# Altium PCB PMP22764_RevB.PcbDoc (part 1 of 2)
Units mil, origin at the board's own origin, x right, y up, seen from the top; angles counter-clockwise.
Board outline 2750 x 1770 mil, 4 copper layers (Top Layer, Signal Layer 1, Signal Layer 2, Bottom Layer), stack 61.2 mil thick; 76 components, 35 nets, 197 pads, 92 vias.
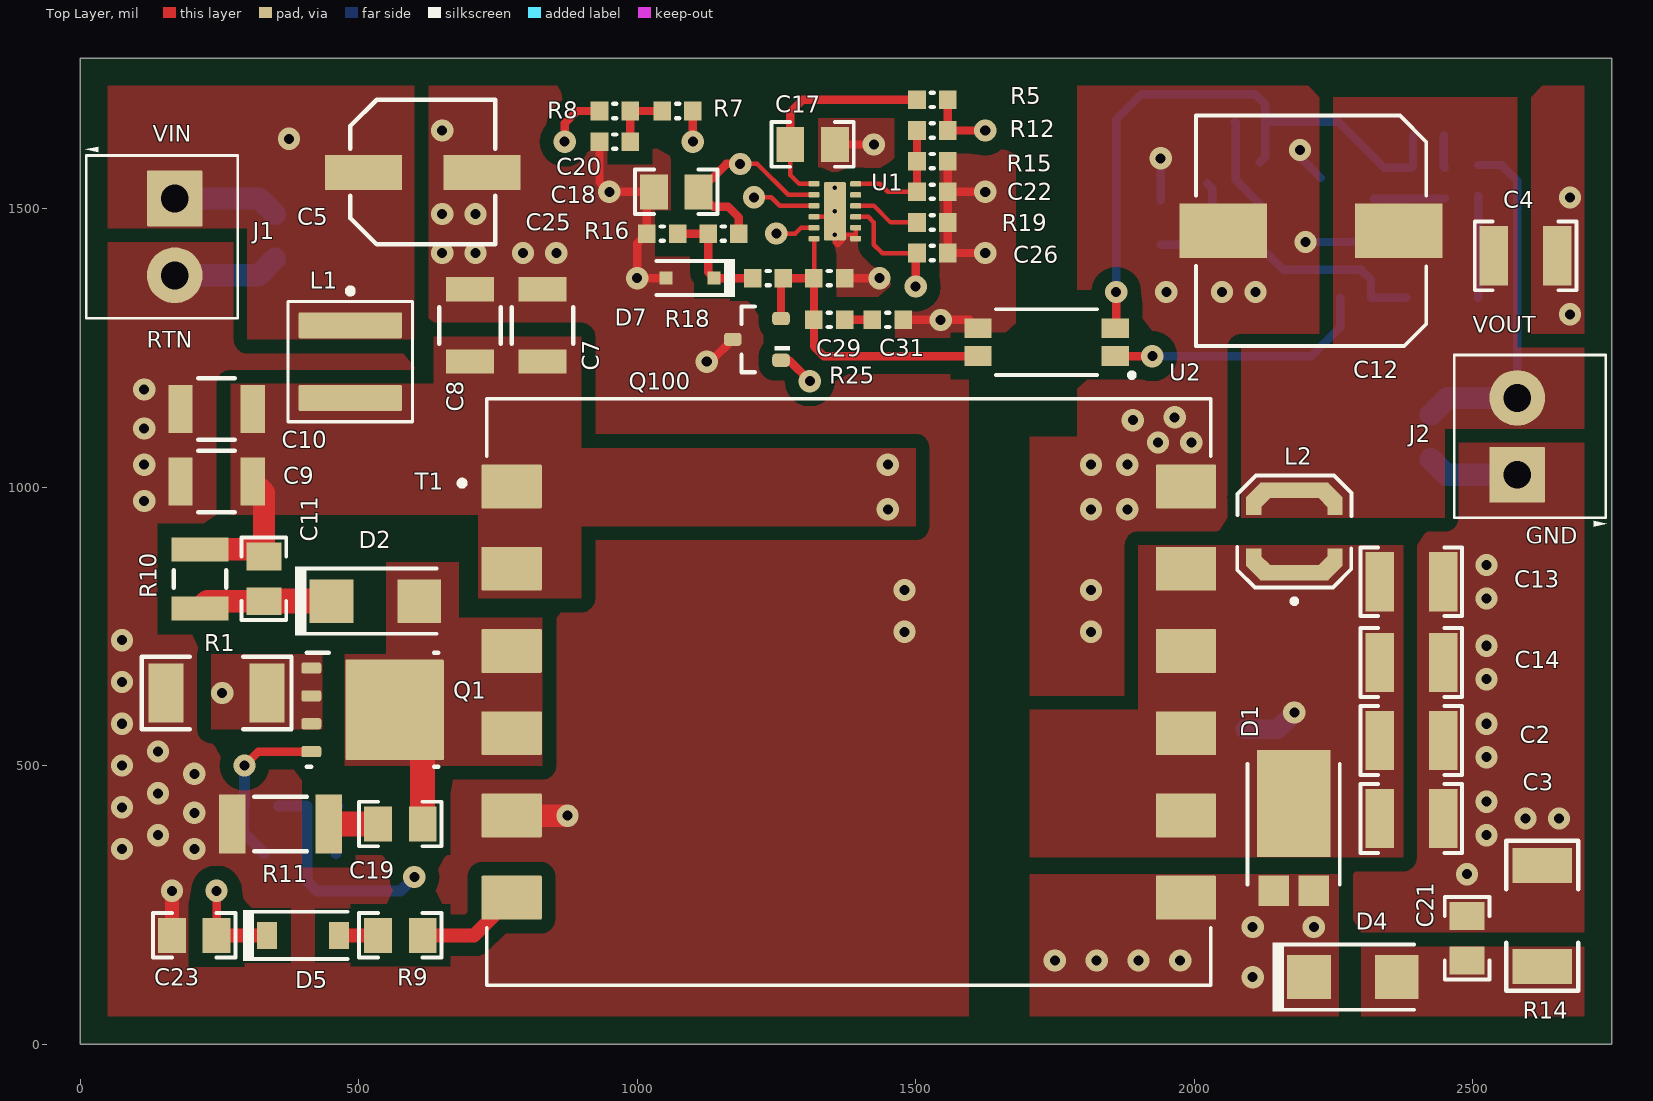
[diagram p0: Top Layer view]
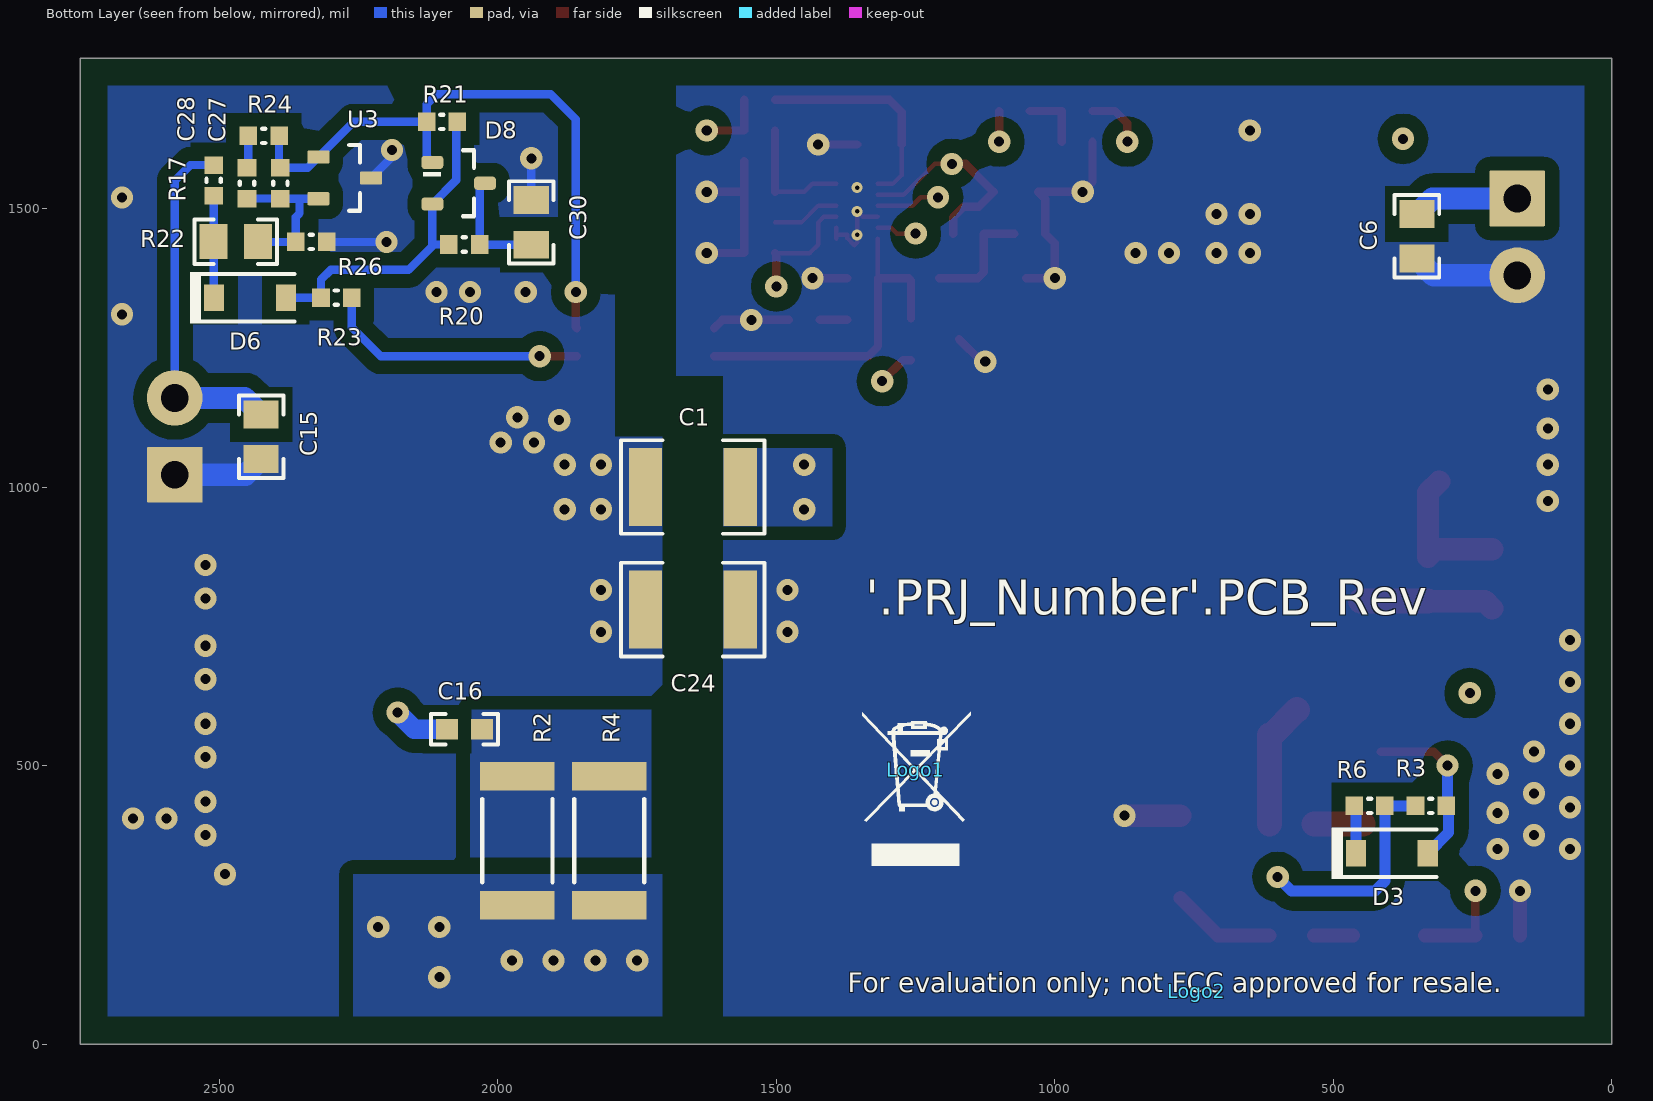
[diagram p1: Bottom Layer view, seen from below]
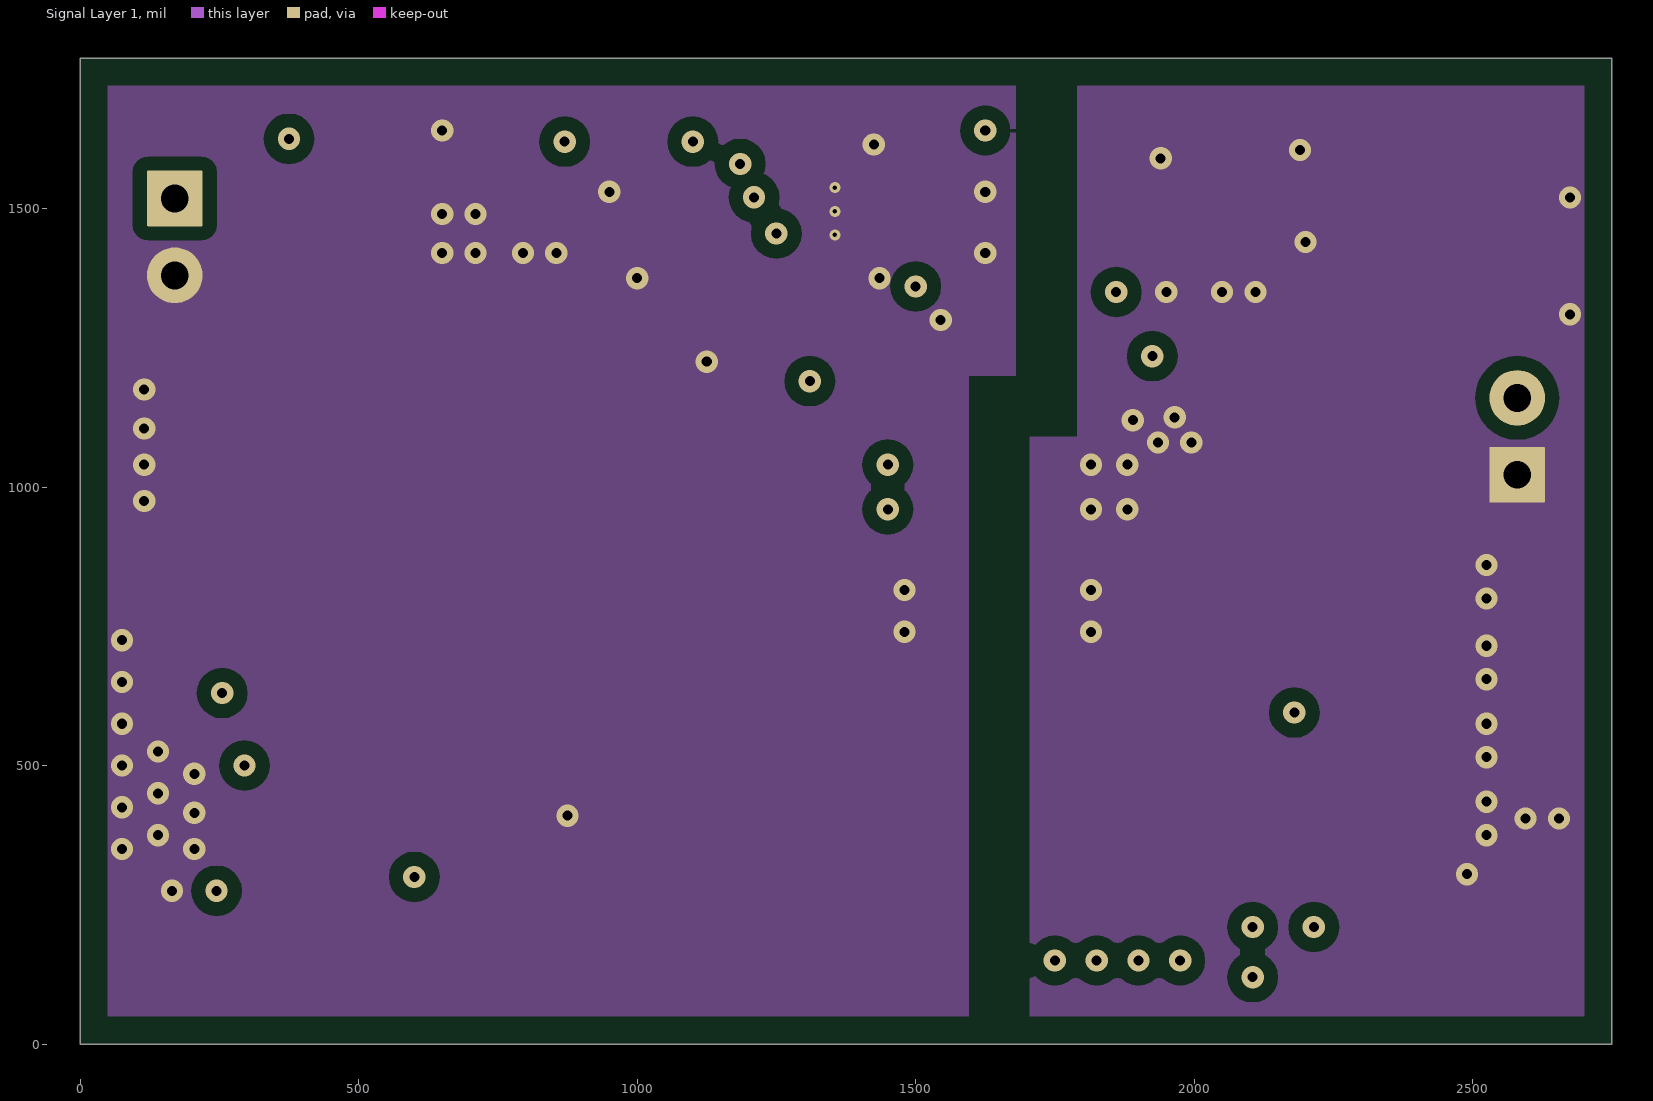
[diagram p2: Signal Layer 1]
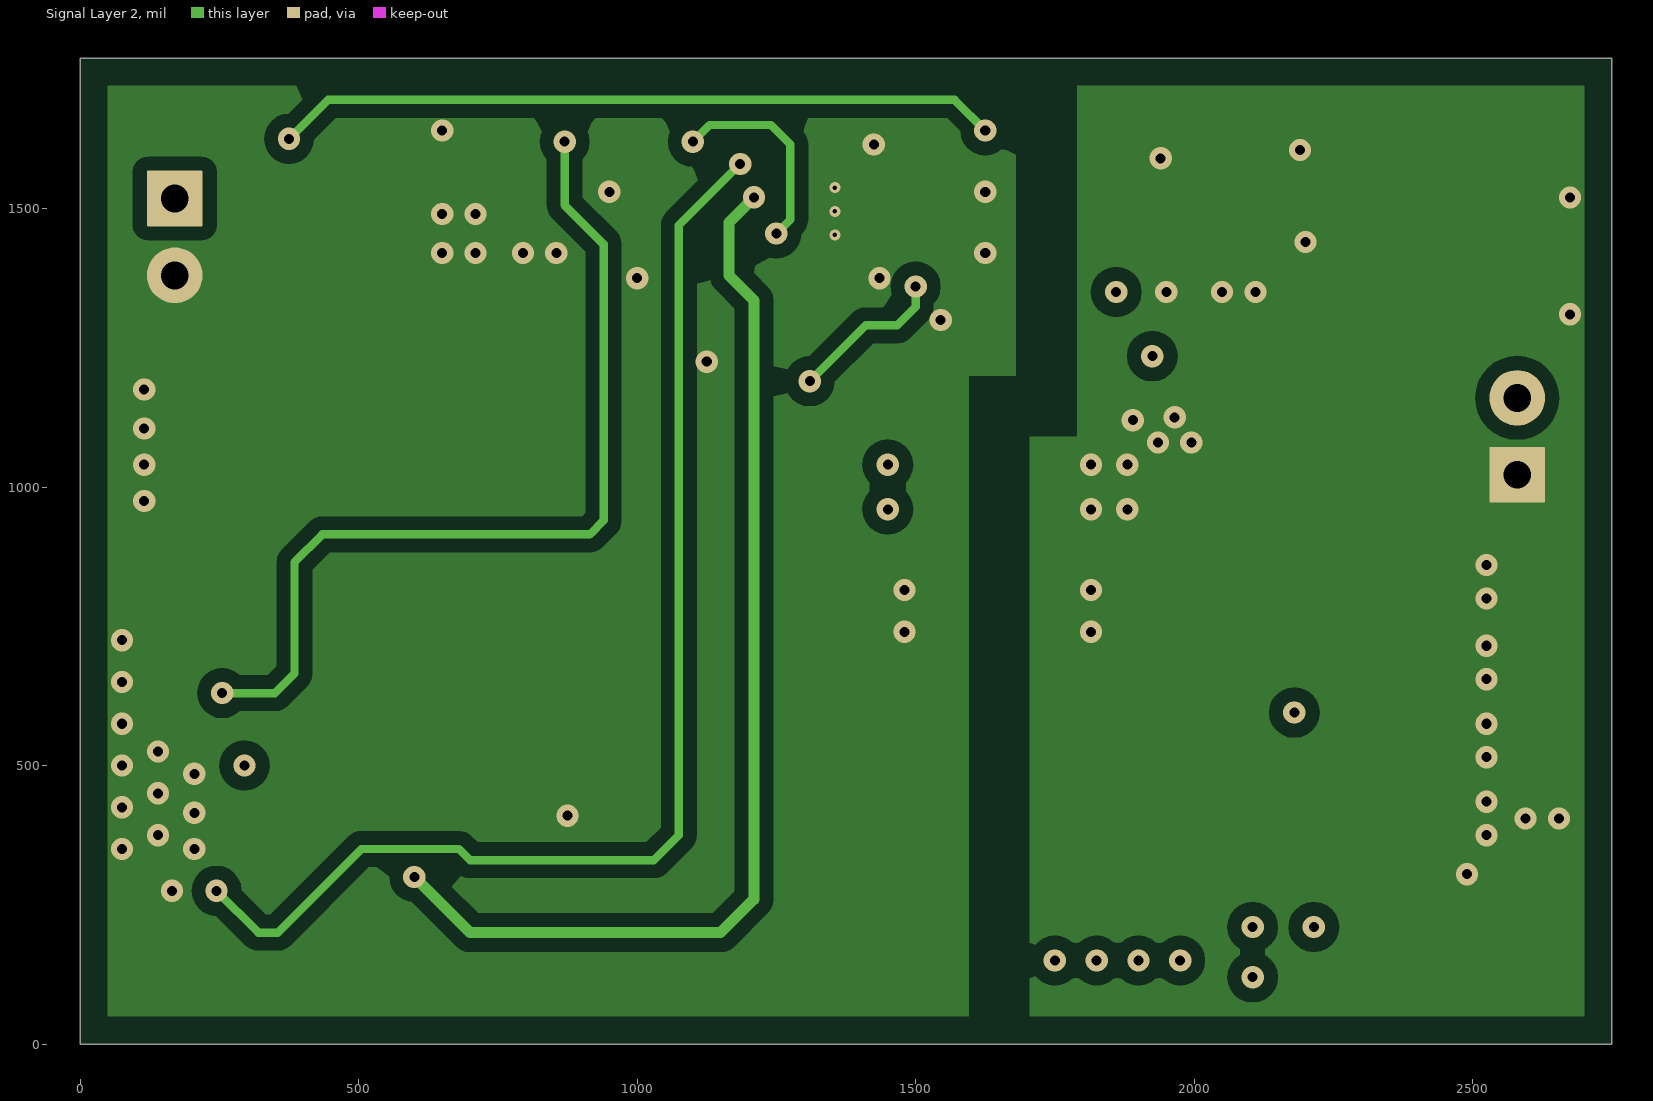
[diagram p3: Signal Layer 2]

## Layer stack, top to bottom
Top Solder: solder mask 0.4, Solder Resist, Dk 3.5
Top Layer: signal copper 2.8
Dielectric1: core 15, FR-4, Dk 4.8
Signal Layer 1: signal copper 2.8
Dielectric 2: prepreg 20, Dk 4.2
Signal Layer 2: signal copper 2.8
Dielectric 3: core 15, FR-4, Dk 4.2
Bottom Layer: signal copper 2.8
Bottom Solder: solder mask 0.4, Solder Resist, Dk 3.5

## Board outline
0,0 2750,0 2750,1770 0,1770

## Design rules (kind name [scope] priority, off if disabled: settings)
AcuteAngle [All] p1: minimum=4.50000000000000E+0001 checktracksonly=FALSE
AssemblyTestPointUsage [All] p1: valid=2
BoardOutlineClearance BoardOutlineClearance_MountingHoles [OnCopper and InComponentClass('Mounting Holes')] p1: gap=39.37 ignorepadtopadclearanceinfootprint=FALSE
BoardOutlineClearance BoardOutlineClearance_Poly [OnCopper and IsPoly] p2: gap=25 ignorepadtopadclearanceinfootprint=FALSE
BoardOutlineClearance [OnCopper and Not InComponentClass('Logo') and not InComponentClass('FiducialMark') and not InRegion(1000,500,4000,800) and not InPoly] p3: gap=50 ignorepadtopadclearanceinfootprint=FALSE
Clearance Clearance_Keepouts [((IsTrack Or IsArc) And Not InPoly) And IsFree and IsKeepOut vs ((IsTrack Or IsArc) And Not InPoly) And IsFree and IsKeepOut] p1: gap=0 ignorepadtopadclearanceinfootprint=FALSE
Clearance Clearance_Poly [InPolygon] p2: gap=25 ignorepadtopadclearanceinfootprint=TRUE
Clearance Clearance_FiducialMark [IsKeepOut and InComponentClass('FiducialMark') vs IsPad and InComponentClass('FiducialMark')] p3: gap=0 ignorepadtopadclearanceinfootprint=FALSE
Clearance [All] p4: gap=7.87 ignorepadtopadclearanceinfootprint=TRUE
ComponentClearance ComponentClearance_MountingHoles_FiducialMarks [InComponentClass('Mounting Holes') vs InComponentClass('FiducialMark')] p1: gap=50 collisioncheckmode=3 verticalgap=10 showdistances=FALSE
ComponentClearance ComponentClearance_Shunt [InComponentClass('Header') vs InComponentClass('Shunt')] p2: gap=0 collisioncheckmode=3 verticalgap=0 showdistances=FALSE
ComponentClearance ComponentClearance_Logo [InComponentClass('Logo')] p3: gap=50 collisioncheckmode=3 verticalgap=10 showdistances=FALSE
ComponentClearance ComponentClearance_ScrewToNut [(HasFootprint('NY PMS 440 0025 PH')) vs (HasFootprint('Keystone_1902C'))] p4: gap=5 collisioncheckmode=3 verticalgap=10 showdistances=FALSE
ComponentClearance ComponentClearance_MountingHoles [InComponentClass('Mounting Holes')] p5: gap=250 collisioncheckmode=3 verticalgap=100000 showdistances=FALSE
ComponentClearance ComponentClearance_SmallPassives [HasFootprint('0201*') or HasFootprint('0402*') or HasFootprint('0508') or HasFootprint('0603*') or HasFootprint('0612') or HasFootprint('0805*') or HasFootprint('0815*') or HasFootprint('0830*') or HasFootprint('1206*') or HasFootprint('1210*') or HasFootprint('1808*') or HasFootprint('1812*') or HasFootprint('1825*') or HasFootprint('2010*') or HasFootprint('2220*') or HasFootprint('2225*') or HasFootprint('2512*') or HasFootprint('2728*') or HasFootprint('3518*') vs HasFootprint('0201*') or HasFootprint('0402*') or HasFootprint('0508') or HasFootprint('0603*') or HasFootprint('0612') or HasFootprint('0805*') or HasFootprint('0815*') or HasFootprint('0830*') or HasFootprint('1206*') or HasFootprint('1210*') or HasFootprint('1808*') or HasFootprint('1812*') or HasFootprint('1825*') or HasFootprint('2010*') or HasFootprint('2220*') or HasFootprint('2225*') or HasFootprint('2512*') or HasFootprint('2728*') or HasFootprint('3518*')] p6: gap=14.96 collisioncheckmode=3 verticalgap=10 showdistances=FALSE
ComponentClearance ComponentClearance_THtoSMT [IsThruComponent vs IsSMTComponent] p7: gap=40 collisioncheckmode=3 verticalgap=30 showdistances=FALSE
ComponentClearance ComponentClearance_THtoTH [IsThruComponent vs IsThruComponent] p8: gap=30 collisioncheckmode=3 verticalgap=30 showdistances=FALSE
ComponentClearance [All] p9: gap=30 collisioncheckmode=3 verticalgap=10 showdistances=FALSE
DiffPairsRouting [All] p1: maxlimit=100 minlimit=10 mostfreqgap=10 toplayer_minwidth=15 toplayer_maxwidth=15 toplayer_prefwidth=15 midlayer1_minwidth=15 midlayer1_maxwidth=15 midlayer1_prefwidth=15 midlayer2_minwidth=15 midlayer2_maxwidth=15 midlayer2_prefwidth=15 bottomlayer_minwidth=15 bottomlayer_maxwidth=15 bottomlayer_prefwidth=15 maxuncoupledlength=1000
FabricationTestPointUsage TestPointUsage [All] p1: valid=2 allowmultiple=FALSE
FabricationTestpoint Testpoint [All] p1: side=3 testpointundercomponent=TRUE minsize=40 maxsize=100 preferedsize=60 minholesize=0 maxholesize=40 preferedholesize=32 testpointgrid=1 allowsidetop=TRUE allowsidebottom=TRUE usegrid=TRUE gridtolerance=0.01
FanoutControl Fanout_LCC [IsLCC] p1: bgadir=Out bgaviamode=Centered fanoutstyle=Auto fanoutdirection=Alternating viagrid=1 // Fanout_LCC (Default Rule)
FanoutControl Fanout_BGA [IsBGA] p2: bgadir=Out bgaviamode=Centered fanoutstyle=Auto fanoutdirection=Alternating viagrid=1 // Fanout_BGA (Default Rule)
FanoutControl Fanout_Default [All] p4: bgadir=Out bgaviamode=Centered fanoutstyle=Auto fanoutdirection=Alternating viagrid=1 // Fanout_Default (Default Rule)
FanoutControl Fanout_Small [(CompPinCount < 5)] p5: bgadir=Out bgaviamode=Centered fanoutstyle=Auto fanoutdirection=OutThenIn viagrid=1 // Fanout_Small (Default Rule)
HoleSize [All] p1: absolutevalues=TRUE maxlimit=251 minlimit=7.87 maxpercent=80.000 minpercent=20.000
MinimumAnnularRing MinimumAnnularRing_ThermalPadVias [IsVia and InAnyComponent] p1: minimumring=5.91
MinimumAnnularRing [All] p2: minimumring=7.87
MinimumSolderMaskSliver MinimumSolderMaskSliver_Logo [InComponentClass('Logo') vs InComponentClass('Logo')] p1: minsoldermaskwidth=0.7
MinimumSolderMaskSliver [All] p2: minsoldermaskwidth=3.94
PlaneConnect [All] p1: planeconnectstyle=Relief reliefexpansion=10 reliefentries=4 reliefconductorwidth=10 reliefairgap=10
PolygonConnect [All] p1: connectstyle=Direct reliefconductorwidth=10 reliefentries=4 polygonreliefangle="90 Angle" airgapwidth=10
RoutingVias ThermalPadVias [IsVia and InAnyComponent] p1: holewidth=7.87 width=19.68 viastyle="Through Hole" minholewidth=7.87 minwidth=19.68 maxholewidth=12.99 maxwidth=23.62
RoutingVias [All] p2: holewidth=18 width=40 viastyle="Through Hole" minholewidth=7.87 minwidth=26 maxholewidth=40 maxwidth=65
SilkToBoardRegionClearance [Not ((IsComment or IsDesignator) And (Hide <> 'False')) and not InRegion(1000,500,4000,800)] p1:
SilkToSilkClearance SilkToSilkClearance_Pb-FreeLogo [(HasFootprint('Pb-Free_Overlay_Medium') OR HasFootprint('Pb-Free_Overlay_Small')) vs (HasFootprint('Pb-Free_Overlay_Medium') OR HasFootprint('Pb-Free_Overlay_Small'))] p1: silktosilkclearance=0
SilkToSilkClearance [All] p2: silktosilkclearance=3.94
SilkToSolderMaskClearance SilkToComponentPadClearance [(IsPad or IsFill or IsRegion) and InAnycomponent] p1: minsilkscreentomaskgap=5 clearancetoexposedcopper=TRUE
SilkToSolderMaskClearance "Silk to Solder Mask Opening" [All] p2: minsilkscreentomaskgap=3.94 clearancetoexposedcopper=FALSE
SolderMaskExpansion [All] p1: expansion=1.97
UnRoutedNet [All] p1: checkbadconnections=TRUE
Width [All] p1: maxlimit=100 minlimit=6 preferedwidth=10 checkconnectedcopper=TRUE
14 further rules are at their usual default settings.

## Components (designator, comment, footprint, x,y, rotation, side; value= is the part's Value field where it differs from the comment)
C1 "Capacitor" 1812_HV 1650,1000 r180 bottom value=2200pF
C2 "Capacitor" 1210_270 2390,545 r180 top value=2.2uF
C3 "Capacitor" 1210_270 2390,405 r180 top value=2.2uF
C4 "Capacitor" 1210_270 2595,1415 r180 top value=2.2uF
C5 "EEHZC1V470P" SM_RADIAL_6.3AMM 615,1565 r0 top value=47uF
C6 "UMK212B7224KG-T" 0805_HV 350,1450 r270 bottom value=0.22uF
C7 "UMK325AB7106KM-T" 1210_280 830,1290 r90 top value=10uF
C8 "UMK325AB7106KM-T" 1210_280 700,1290 r90 top value=10uF
C9 "UMK325AB7106KM-T" 1210_280 245,1010 r180 top value=10uF
C10 "UMK325AB7106KM-T" 1210_280 245,1140 r180 top value=10uF
C11 "UMK212B7224KG-T" 0805_HV 330,835 r270 top value=0.22uF
C12 "EEHZC1J560P" SM_RADIAL_10BMM 2210,1460 r180 top value=56uF
C13 "Capacitor" 1210_270 2390,830 r0 top value=2.2uF
C14 "Capacitor" 1210_270 2390,685 r0 top value=2.2uF
C15 "Capacitor" 0805_HV 2425,1090 r90 bottom value=0.1uF
C16 "C1608C0G2E221J080AA" 0603 2060,565 r180 bottom value=220pF
C17 "UMK212B7224KG-T" 0805_HV 1315,1615 r180 top value=0.22uF
C18 "TMK212B7105KG-T" 0805_HV 1070,1530 r180 top value=1uF
C19 "Capacitor" 0805_HV 575,395 r180 top value=100pF
C20 "885012206081" 0603L 960,1620 r0 top value=470pF
C21 "QMK212B7103KG-T" 0805_HV 2490,190 r90 top value=0.01uF
C22 "GRM1885C1H470JA01D" 0603L 1530,1530 r180 top value=47pF
C23 "TMK212B7105KG-T" 0805_HV 205,195 r0 top value=1uF
C24 "Capacitor" 1812_HV 1650,780 r180 bottom value=2200pF
C25 "885012206071" 0603L 1045,1455 r180 top value=0.1uF
C26 "C1608X7R1E224K080AC" 0603L 1530,1420 r0 top value=0.22uF
C27 "C0603C220J5GACTU" 0603L 2390.39,1545.46 r90 bottom value=22pF
C28 "GRM188R71E473KA01D" 0603L 2450.39,1545.46 r90 bottom value=0.047uF
C29 "885012206083" 0603L 1345,1375 r180 top value=1000pF
C30 "TMK212B7105KG-T" 0805_HV 1940,1475 r270 bottom value=1uF
C31 "885012206071" 0603L 1450,1300 r0 top value=0.1uF
D1 "PDU620-13" POWERDI5 2178.78,353.39 r90 top value=200V
D2 "ES2DA-13-F" SMA 530,795 r0 top value=200V
D3 "MMSD4148T1G" SOD-123 395,342.5 r180 bottom value=100V
D4 "ES2DA-13-F" SMA 2285,120 r0 top value=200V
D5 "MMSD4148T1G" SOD-123 400,195 r0 top value=100V
D6 "MMSZ5259B-7-F" SOD-123 2445,1340 r180 bottom value=39V
D7 "MMSZ5231BS-7-F" SOD-323 1095,1375 r180 top value=5.1V
D8 "BAT54S-7-F" SOT-23 2070.39,1545.46 r180 bottom value=30V
J1 "ED555/2DS" TERM_BLK_ED555-2DS 170,1518 r270 top
J2 "Receptacle_2x1" TERM_BLK_ED555-2DS 2580,1022 r90 top
L1 "XEL5050-332MEB" FP-XEL5050-332MEB_SMT_IND_5MM48_5MM28-MFG 485,1225 r270 top value=3.3uH
L2 "LPS4012-331MLB" LPS4012 2180,920 r90 top value=330nH
Logo1 "WEEE logo" WEEE_Minimum 1250,492.22 r180 bottom
Logo2 "FCC disclaimer" FCC_disclaimer 745,95 r180 bottom
Q1 "CSD19531Q5A" DQJ0008A 525.04,600 r0 top value=100V
Q100 "FMMT718TA" SOT-23L 1215,1265 r180 top value="20 V"
R1 "RC1210JR-0710KL" 1210L 215,835 r270 top value=10k
R2 "CRCW251268R0JNEG" 2512 1965,365 r90 bottom value=68
R3 "CRCW060320R0JNEA" 0603L 325,427.5 r180 bottom value=20
R4 "CRCW251268R0JNEG" 2512 1800,365 r90 bottom value=68
R5 "Resistor" 0603L 1530,1695 r0 top value=0
R6 "Resistor" 0603L 435,427.5 r0 bottom value=0
R7 "Resistor" 0603L 1072.56,1675 r180 top value=0
R8 "CRCW0603301RFKEA" 0603L 960,1675 r180 top value=301
R9 "CRCW080510R0JNEA" 0805_HV 575,195 r180 top value=10
R10 "PMR50HZPFU10L0" 2010 245,630 r0 top value=0.01
R11 "Resistor" 2010L 360,395 r0 top value=75
R12 "CRCW0603324KFKEA" 0603L 1530,1640 r180 top value=324k
R14 "CRCW201039K0JNEF" 2010 2625,230 r90 top value=39k
R15 "CRCW060329K4FKEA" 0603L 1530,1585 r0 top value=29.4k
R16 "CRCW06031K00FKEA" 0603L 1155,1455 r0 top value=1.00k
R17 "Resistor" 0603L 2510.39,1550.46 r270 bottom value=0
R18 "CRCW06032K49FKEA" 0603L 1235,1375 r0 top value=2.49k
R19 "CRCW060386K6FKEA" 0603L 1530,1475 r0 top value=86.6k
R20 "CRCW060310K0FKEA" 0603L 2060.39,1435.46 r180 bottom value=10.0k
R21 "CRCW060310K0FKEA" 0603L 2100.39,1655.46 r0 bottom value=10.0k
R22 "CRCW080549K9FKEA" 0805_HV 2470.39,1440.46 r180 bottom value=49.9k
R23 "CRCW06032K49FKEA" 0603L 2290,1340 r180 bottom value=2.49k
R24 "CRCW060340K2FKEA" 0603L 2420.39,1630.46 r0 bottom value=40.2k
R25 "CRCW06031K00FKEA" 0603L 1345,1300 r180 top value=1.00k
R26 "CRCW06032K32FKEA" 0603L 2335,1440 r180 bottom value=2.32k
T1 "ZB1368-AL" FP-ZB1368-AL_PTH_XFRMR_33MM02_26MM75-MFG 1380,631.85 r0 top
U1 "LM51551DSSR" DSS0012B 1355,1495 r0 top
U2 "VOS617A-7X001T" SSOP-4_VISHAY 1735,1260 r180 top
U3 "TL431LIAIDBZR" DBZ0003A_N 2275,1555 r180 bottom

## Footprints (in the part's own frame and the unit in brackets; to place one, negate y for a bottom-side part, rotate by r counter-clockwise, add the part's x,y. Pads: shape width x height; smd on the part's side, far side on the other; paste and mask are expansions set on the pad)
0603 [mm] "0603 from SM-752 data"
  rect 1x0.95 smd: 1(-0.8,0) 2(0.8,0)
  silkscreen extent -1.52,-0.69 1.52,0.69, body extent -0.87,-0.47 0.87,0.47, height 1
0603L [mm] "0603 from SM-752 data"
  rect 0.8x0.85 smd: 1(-0.7,0) 2(0.7,0)
  silkscreen extent -0.07,-0.33 0.07,0.33, body extent -0.87,-0.47 0.87,0.47, height 1
0805_HV [mil] "0805 with 30mil clearance between pads"
  rect 50x63 smd: 1(-40,0) 2(40,0)
  silkscreen extent -74,-40 74,40, body extent -43,-29 43,29, height 57
1210_270 [mm] "1210"
  rect 1.3x2.7 smd: 1(-1.45,0) 2(1.45,0)
  silkscreen extent -2.32,-1.57 2.32,1.57, body extent -1.7,-1.35 1.7,1.35, height 2.7
1210_280 [mm] "SMD, 2-Leads, Body 3.6x2.8mm, Height 2.8mm"
  rect 1.1x2.2 smd: 1(-1.65,0) 2(1.65,0)
  silkscreen extent -0.84,-1.4 0.84,1.4, body extent -1.8,-1.4 1.8,1.4, height 2.8
1210L [mm] "1210 from SM-752 data"
  rect 1.1x2.6 smd: 1(-1.35,0) 2(1.35,0)
  silkscreen extent -0.4,-1.2 0.4,1.2, body extent -1.7,-1.35 1.7,1.35, height 1.35
1812_HV [mil] "PRG recommended land pattern"
  rect 60x140 smd: 1(-85,0) 2(85,0)
  silkscreen extent -129,-84 129,84, body extent -94,-67 94,67, height 53
2010 [mm] "Chip Capacitor, Body 5.08x2.54mm, IPC Medium Density"
  rect 1.6x2.7 smd: 1(-2.3,0) 2(2.3,0)
  silkscreen extent -3.42,-1.65 3.42,1.65, body extent -2.73,-1.45 2.73,1.45, height 1.66
2010L [mm]
  rect 1.2x2.7 smd: 1(-2.2,0) 2(2.2,0)
  silkscreen extent -1.2,-1.25 1.2,1.25, body extent -2.73,-1.45 2.73,1.45, height 1.66
2512 [mm] "Chip Resistor, Body 6.3x3.2mm, IPC Medium Density"
  rect 1.3x3.4 smd: 1(-2.95,0) 2(2.95,0)
  silkscreen extent -1.9,-1.6 1.9,1.6, body extent -3.22,-1.67 3.22,1.67, height 0.71
DBZ0003A_N [mm] "SOT23, 3-Leads, Body 2.9x1.3mm, Pitch 0.95mm, Lead Span 2.4mm, IPC Medium Density"
  rrect17% 1x0.6 smd: 1(-1.2,0.95) 2(-1.2,-0.95) 3(1.2,0)
  silkscreen extent 0.2,-1.5 0.7,1.5, body extent -1.26,-1.46 1.26,1.46, height 0.98
DQJ0008A [mm] "SMD, 8-Leads, Body 5.75x4.9mm"
  rrect39% 0.91x0.51 smd paste-0.05 mask-0.05: 1(-2.795,1.905) 2(-2.795,0.635) 3(-2.795,-0.635) 4(-2.795,-1.905) 5(2.795,-1.905) 6(2.795,-0.635) 7(2.795,0.635) 8(2.795,1.905)
  rrect8% 1.58x1.25 on Top Paste: 9(-0.38,-1.45) 9(-0.38,0) 9(-0.38,1.45) 9(1.4,-1.45) 9(1.4,0) 9(1.4,1.45)
  rrect3% 3.48x4.47 on Top Solder: 9(0.55,0)
  rrect2% 4.49x4.57 smd paste-2.5 mask-2.5: 9(1.005,0)
  silkscreen extent -3,-2.6 3,2.6, body extent -3.13,-2.45 3.13,2.45, height 1.15
DSS0012B [mm] "WSON-10"
  rrect40% 0.5x0.25 smd: 1(-0.95,1.25) 2(-0.95,0.75) 3(-0.95,0.25) 4(-0.95,-0.25) 5(-0.95,-0.75) 6(-0.95,-1.25) 7(0.95,-1.25) 8(0.95,-0.75) 9(0.95,-0.25) 10(0.95,0.25) 11(0.95,0.75) 12(0.95,1.25)
  rrect11% 1x2.65 smd paste-0.5: 13(0,0)
  body extent -1,-1.5 1,1.5, height 0.81
FCC_disclaimer [mil]
FP-XEL5050-332MEB_SMT_IND_5MM48_5MM28-MFG [mm]
  rrect8% 1.18x4.7 smd paste+0 mask+0: 1(-1.655,0) 2(1.655,0)
  silkscreen extent -3.35,-2.84 2.74,2.84, body extent -2.84,-2.94 2.84,2.94, height 0.25
FP-ZB1368-AL_PTH_XFRMR_33MM02_26MM75-MFG [mm]
  rrect5% 2.75x2 smd paste+0 mask+0: 1(-15.375,9.375) 2(-15.375,5.625) 3(-15.375,1.875) 4(-15.375,-1.875) 5(-15.375,-5.625) 6(-15.375,-9.375) 7(15.375,-9.375) 8(15.375,-5.625) 9(15.375,-1.875) 10(15.375,1.875) 11(15.375,5.625) 12(15.375,9.375)
  silkscreen extent -17.76,-13.37 16.51,13.37, body extent -16.85,-13.47 16.85,13.47, height 0.25
LPS4012 [mm] "Coilcraft recommended land pattern.  Document 433-2, rev 10/20/08"
  rect 0.7x3.124 smd: 1(-1.881,0) 2(1.881,0)
  rect 0.902x0.801 smd rot 45: 1(-1.592,1.605) 2(1.592,-1.605)
  rect 0.902x0.801 smd rot 135: 1(-1.592,-1.605) 2(1.592,1.605)
  rect 0.812x0.7 smd: 1(-1.168,1.85) 1(-1.168,-1.85) 2(1.168,1.85) 2(1.168,-1.85)
  silkscreen extent -3.26,-2.6 2.55,2.6, body extent -2.05,-2.05 2.05,2.05, height 1.22
POWERDI5 [mm] "Diodes Inc recommended land pattern, ap02001.pdf rev 60"
  rect 1.4x1.39 smd: 1(-1.991,0.92) 2(-1.991,-0.92)
  rect 4.86x3.36 smd: 3(1.991,0)
  silkscreen extent -1.7,-2.1 3.8,2.1, body extent -2.27,-2.03 4.33,2.03, height 1.17
SM_RADIAL_6.3AMM [mm] "Nichicon 6.3x5.8"
  rect 3.5x1.6 smd: 1(-2.7,0) 2(2.7,0)
  silkscreen extent -3.3,-3.29 3.3,3.31, body extent -3.5,-3.3 3.5,3.3, height 6.11
SM_RADIAL_10BMM [mm] "Nichicon 10x10"
  rect 4x2.5 smd: 1(-4,0) 2(4,0)
  silkscreen extent -5.25,-5.25 5.25,5.25, body extent -5.25,-5.25 5.25,5.25, height 10.5
SMA [mm] "Molded Diode, 2-Leads, Body 4.3x2.6mm, IPC Medium Density, based on OnSemi component dimensions and land pattern"
  rect 2x2 smd: 1(-2,0) 2(2,0)
  silkscreen extent -3.66,-1.57 2.79,1.57, body extent -2.6,-1.3 2.6,1.3, height 2.42
SOD-123 [mm] "On Semi recommended land pattern"
  rect 0.915x1.22 smd: 1(-1.637,0) 2(1.637,0)
  silkscreen extent -2.74,-1.17 2.03,1.17, body extent -1.93,-0.9 1.93,0.9, height 1.35
SOD-323 [mm] "NXP recommended land pattern"
  rect 0.6x0.6 smd paste-0.05: 1(-1.1,0) 2(1.1,0)
  silkscreen extent -2.06,-0.86 1.53,0.86, body extent -1.3,-0.67 1.3,0.68, height 1.1
SOT-23 [mm] "SOT23, 3-Leads, Body 2.9x1.3mm, Pitch 0.95mm, Lead Span 2.5mm, IPC Medium Density"
  rrect50% 1x0.6 smd: 1(-1.2,0.95) 2(-1.2,-0.95) 3(1.2,0)
  silkscreen extent -1.63,-1.5 0.7,1.5, body extent -1.16,-1.45 1.21,1.45, height 1
SOT-23L [mm] "SOT23, 3-Leads, Body 2.9x1.3mm, Pitch 0.95mm, Lead Span 2.5mm, IPC High Density"
  rrect50% 0.8x0.6 smd: 1(-1.1,0.95) 2(-1.1,-0.95) 3(1.1,0)
  silkscreen extent -1.5,-1.5 0.7,1.5, body extent -1.16,-1.45 1.21,1.45, height 1
SSOP-4_VISHAY [mm] "Vishay Recommened"
  rect 1.25x0.9 smd: 1(-3.125,0.635) 2(-3.125,-0.635) 3(3.125,-0.635) 4(3.125,0.635)
  silkscreen extent -3.98,-1.5 2.3,1.59, body extent -3.5,-1.45 3.5,1.45, height 2.42
TERM_BLK_ED555-2DS [mil]
  rrect4% 100x100 hole 50: 1(0,0)
  round 100 hole 50: 2(138,0)
  silkscreen extent -93,-161 215,113, body extent -69,-150 207,106, height 323
WEEE_Minimum [mil] "WEEElie bin"
  silkscreen extent -95,-172 99,104

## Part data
C1 C24: library part CMP-0009358-2, "CAP, CERM, 2200 pF, 2000 V, +/- 10%, X7R, 1812", Cap_Case=1812, Manufacturer=TDK, PartNumber=C4532X7R3D222K130KA, Supplier Part Number 1=445-2389-1-ND, TempCo=X7R, Tolerance_%=10%, Value1=Unknown, Value2=2000V, ValueDisplayed=2200pF
C2 C3 C4 C13 C14: library part CMP-0009232-2, "CAP, CERM, 2.2 uF, 100 V, +/- 10%, X7R, 1210", Cap_Case=1210, Manufacturer=MuRata, PartNumber=GRM32ER72A225KA35L, Supplier Part Number 1=490-3385-1-ND, TempCo=X7R, Tolerance_%=10%, Value1="0.007 ohm", Value2=100V, ValueDisplayed=2.2uF
C5: library part CMP-0012607-3, "CAP, Polymer Hybrid, 47 uF, 35 V, +/- 20%, 60 ohm, 6.3x5.8 SMD", Manufacturer=Panasonic, Supplier Part Number 1=P15473CT-ND, Tolerance_%=20%, Value1="60 ohm", Value2=35V, ValueDisplayed=47uF
C6 C11 C17: library part CMP-0008422-2, "CAP, CERM, 0.22 uF, 50 V, +/- 10%, X7R, 0805", Cap_Case=0805, Manufacturer="Taiyo Yuden", Supplier Part Number 1=587-1287-1-ND, TempCo=X7R, Tolerance_%=10%, Value1=Unknown, Value2=50V, ValueDisplayed=0.22uF
C7 C8 C9 C10: library part CMP-0009259-2, "CAP, CERM, 10 uF, 50 V, +/- 10%, X7R, 1210", Cap_Case=1210, Manufacturer="Taiyo Yuden", Supplier Part Number 1=587-3167-1-ND, TempCo=X7R, Tolerance_%=10%, Value1=Unknown, Value2=50V, ValueDisplayed=10uF
C12: library part CMP-0012603-3, "CAP, Polymer Hybrid, 56 uF, 63 V, +/- 20%, 30 ohm, 10x10 SMD", Manufacturer=Panasonic, Supplier Part Number 1=P15469CT-ND, Tolerance_%=20%, Value1="30 ohm", Value2=63V, ValueDisplayed=56uF
C15: library part CMP-0007886-2, "CAP, CERM, 0.1 uF, 100 V, +/- 10%, X7R, 0805", Cap_Case=0805, Manufacturer=TDK, PartNumber=C2012X7R2A104K125AA, Supplier Part Number 1=445-1418-1-ND, TempCo=X7R, Tolerance_%=10%, Value1="0.020726 ohm", Value2=100V, ValueDisplayed=0.1uF
C16: library part CMP-0006996-4, "CAP, CERM, 220 pF, 250 V, +/- 5%, C0G/NP0, 0603", Cap_Case=0603, Manufacturer=TDK, Supplier Part Number 1=445-2316-1-ND, TempCo=C0G/NP0, Tolerance_%=5%, Value1=Unknown, Value2=250V, ValueDisplayed=220pF
C18 C23 C30: library part CMP-0008412-2, "CAP, CERM, 1 uF, 25 V, +/- 10%, X7R, 0805", Cap_Case=0805, Manufacturer="Taiyo Yuden", Supplier Part Number 1=587-1281-1-ND, TempCo=X7R, Tolerance_%=10%, Value1=Unknown, Value2=25V, ValueDisplayed=1uF
C19: library part CMP-0008236-2, "CAP, CERM, 100 pF, 250 V, +/- 5%, C0G/NP0, 0805", Cap_Case=0805, Manufacturer=MuRata, PartNumber=GRM21A5C2E101JW01D, Supplier Part Number 1=490-5542-1-ND, TempCo=C0G/NP0, Tolerance_%=5%, Value1=Unknown, Value2=250V, ValueDisplayed=100pF
C20: library part CMP-0006834-5, "CAP, CERM, 470 pF, 50 V, +/- 10%, X7R, 0603", Cap_Case=0603, Manufacturer="Wurth Elektronik", Supplier Part Number 1=710-885012206081, TempCo=X7R, Tolerance_%=10%, Value1=Unknown, Value2=50V, ValueDisplayed=470pF
C21: library part CMP-0008408-2, "CAP, CERM, 0.01 uF, 250 V, +/- 10%, X7R, 0805", Cap_Case=0805, Manufacturer="Taiyo Yuden", Supplier Part Number 1=587-1271-1-ND, TempCo=X7R, Tolerance_%=10%, Value1=Unknown, Value2=250V, ValueDisplayed=0.01uF
C22: library part CMP-0007220-4, "CAP, CERM, 47 pF, 50 V, +/- 5%, C0G/NP0, 0603", Cap_Case=0603, Manufacturer=MuRata, Supplier Part Number 1=490-1419-1-ND, TempCo=C0G/NP0, Tolerance_%=5%, Value1=Unknown, Value2=50V, ValueDisplayed=47pF
C25 C31: library part CMP-0006832-5, "CAP, CERM, 0.1 uF, 25 V, +/- 10%, X7R, 0603", Cap_Case=0603, Manufacturer="Wurth Elektronik", Supplier Part Number 1=710-885012206071, TempCo=X7R, Tolerance_%=10%, Value1=Unknown, Value2=25V, ValueDisplayed=0.1uF
C26: library part CMP-0007042-4, "CAP, CERM, 0.22 uF, 25 V, +/- 10%, X7R, 0603", Cap_Case=0603, Manufacturer=TDK, Supplier Part Number 1=445-5191-1-ND, TempCo=X7R, Tolerance_%=10%, Value1=Unknown, Value2=25V, ValueDisplayed=0.22uF
C27: library part CMP-0006892-4, "CAP, CERM, 22 pF, 50 V, +/- 5%, C0G/NP0, 0603", Cap_Case=0603, Manufacturer=Kemet, Supplier Part Number 1=399-1053-1-ND, TempCo=C0G/NP0, Tolerance_%=5%, Value1=Unknown, Value2=50V, ValueDisplayed=22pF
C28: library part CMP-0007423-4, "CAP, CERM, 0.047 uF, 25 V, +/- 10%, X7R, 0603", Cap_Case=0603, Manufacturer=MuRata, Supplier Part Number 1=490-1522-1-ND, TempCo=X7R, Tolerance_%=10%, Value1=Unknown, Value2=25V, ValueDisplayed=0.047uF
C29: library part CMP-0064933-4, "CAP, CERM, 1000 pF, 50 V,+/- 10%, X7R, 0603", Cap_Case=0603, Manufacturer="Wurth Elektronik", Supplier Part Number 1=732-8001-1-ND, TempCo=X7R, Tolerance_%=10%, Value1=Unknown, Value2=50V, ValueDisplayed=1000pF
D1: library part CMP-0077019-2, "Diode, Ultrafast, 200 V, 6 A, PowerDI5", Manufacturer="Diodes Inc.", Value1=6A, Value2=0.94V
D2 D4: library part CMP-0076892-2, "Diode, Superfast Rectifier, 200 V, 2 A, SMA", Manufacturer="Diodes Inc.", Value1=2A, Value2=0.92V
D3 D5: library part CMP-0029032-2, "Diode, Switching, 100 V, 0.2 A, SOD-123", Manufacturer="ON Semiconductor", Value1=0.2A, Value2=1V
D6: library part CMP-0005764-4, "Diode, Zener, 39 V, 500 mW, SOD-123", Manufacturer="Diodes Inc.", Power_W=500mW, Value1=0.5W
D7: library part CMP-0005854-3, "Diode, Zener, 5.1 V, 200 mW, SOD-323", Manufacturer="Diodes Inc.", Power_W=200mW, Value1=0.2W
D8: library part CMP-0028456-2, "Diode, Schottky, 30 V, 0.2 A, SOT-23", Manufacturer="Diodes Inc.", Value1=0.2A, Value2=0.65V
J1: library part CMP-0074913-1, "Terminal Block, 3.5mm Pitch, 2x1, TH", Color=Grey, Current_A=6A, Manufacturer="On-Shore Technology", Supplier Part Number 1=ED1514-ND, Voltage_V=150V
J2: library part CMP-0074913-1, "Terminal Block, 3.5mm Pitch, 2x1, TH", Color=Grey, Current_A=6A, Manufacturer="On-Shore Technology", PartNumber=ED555/2DS, Supplier Part Number 1=ED1514-ND, Voltage_V=150V
L1: library part CMP-0090124-1, "Shielded Power Inductor, 3.3uH, ±20%, 7.8A, 14.6mO max", Manufacturer=Coilcraft, Operating Temperature Range="to +165°C", Self Resonant Frequency=31MHz, Test Frequency=1MHz, Tolerance_%=20%
L2: library part CMP-0060464-1, "Inductor, Shielded Drum Core, Ferrite, 330 nH, 3 A, 0.03 ohm, SMD", Manufacturer=Coilcraft, Value1="0.03 ohm", Value2=3A, ValueDisplayed=330nH
Logo1: library part CMP-0074769-1
Logo2: library part CMP-0074847-1, "FCC_disclaimer"
Q1: library part CMP-0000956-2, "MOSFET, N-CH, 100 V, 16 A, DQJ0008A (VSONP-8)", Alternate Manufacturer=None, Manufacturer="Texas Instruments", Supplier Part Number 1=CSD19531Q5A-ND, Value2="36 nC"
Q100: library part CMP-0000330-2, "Transistor, PNP, 20 V, 1.5 A, SOT-23", Manufacturer="Diodes Inc.", Supplier Part Number 1=FMMT718CT-ND, Value1="1.5 A", Value2=6
R1: library part CMP-0083442-1, "RES, 10 k, 5%, 0.5 W, 1210", Manufacturer=Yageo, Power_W=500mW, TempCo="100 ppm/C", Tolerance_%=5%, Value2=0.5W, Value_Code=10k0, ValueDisplayed=10k
R2 R4: library part CMP-0015995-3, "RES, 68, 5%, 1 W, AEC-Q200 Grade 0, 2512", Manufacturer=Vishay-Dale, Power_W=1W, Supplier Part Number 1=541-68XCT-ND, TempCo="200 ppm/C", Tolerance_%=5%, Value_Code=68R0, ValueDisplayed=68
R3: library part CMP-0025754-4, "RES, 20, 5%, 0.1 W, AEC-Q200 Grade 0, 0603", Manufacturer=Vishay-Dale, Power_W=100mW, Supplier Part Number 1=541-20GCT-ND, TempCo="200 ppm/C", Tolerance_%=5%, Value2=0.1W, Value_Code=20R0, ValueDisplayed=20
R5 R6 R7 R17: library part CMP-0025697-4, "RES, 0, 5%, 0.1 W, AEC-Q200 Grade 0, 0603", Manufacturer=Vishay-Dale, PartNumber=CRCW06030000Z0EA, Power_W=100mW, Supplier Part Number 1=541-0.0GCT-ND, TempCo="200 ppm/C", Tolerance_%=5%, Value2=0.1W, Value_Code=0000, ValueDisplayed=0
R8: library part CMP-0022321-5, "RES, 301, 1%, 0.1 W, AEC-Q200 Grade 0, 0603", Manufacturer=Vishay-Dale, Power_W=100mW, Supplier Part Number 1=541-301HCT-ND, TempCo="100 ppm/C", Tolerance_%=1%, Value2=0.1W, Value_Code=301R, ValueDisplayed=301
R9: library part CMP-0020448-3, "RES, 10, 5%, 0.125 W, AEC-Q200 Grade 0, 0805", Manufacturer=Vishay-Dale, Power_W=125mW, Supplier Part Number 1=541-10ACT-ND, TempCo="200 ppm/C", Tolerance_%=5%, Value2=0.125W, Value_Code=10R0, ValueDisplayed=10
R10: library part CMP-0016536-2, "RES, 0.01, 1%, 1 W, 2010", Manufacturer=Rohm, Power_W=1W, Supplier Part Number 1=RHM.010ASCT-ND, TempCo="100 ppm/C", Tolerance_%=1%, Value_Code=R010, ValueDisplayed=0.01
R11: library part CMP-0016178-3, "RES, 75, 5%, 0.75 W, AEC-Q200 Grade 0, 2010", Manufacturer=Vishay-Dale, PartNumber=CRCW201075R0JNEF, Power_W=750mW, Supplier Part Number 1=541-75.0WCT-ND, TempCo="200 ppm/C", Tolerance_%=5%, Value2=0.75W, Value_Code=75R0, ValueDisplayed=75
R12: library part CMP-0022332-4, "RES, 324 k, 1%, 0.1 W, AEC-Q200 Grade 0, 0603", Manufacturer=Vishay-Dale, Power_W=100mW, Supplier Part Number 1=541-324KHCT-ND, TempCo="100 ppm/C", Tolerance_%=1%, Value2=0.1W, Value_Code=324k
R14: library part CMP-0016129-3, "RES, 39 k, 5%, 0.75 W, AEC-Q200 Grade 0, 2010", Manufacturer=Vishay-Dale, Power_W=750mW, Supplier Part Number 1=541-39KWCT-ND, TempCo="200 ppm/C", Tolerance_%=5%, Value2=0.75W, Value_Code=39k0, ValueDisplayed=39k
R15: library part CMP-0022266-4, "RES, 29.4 k, 1%, 0.1 W, AEC-Q200 Grade 0, 0603", Manufacturer=Vishay-Dale, Power_W=100mW, Supplier Part Number 1=541-29.4KHCT-ND, TempCo="100 ppm/C", Tolerance_%=1%, Value2=0.1W, Value_Code=29k4, ValueDisplayed=29.4k
R16 R25: library part CMP-0022109-5, "RES, 1.00 k, 1%, 0.1 W, AEC-Q200 Grade 0, 0603", Manufacturer=Vishay-Dale, Power_W=100mW, Supplier Part Number 1=541-1.00KHCT-ND, TempCo="100 ppm/C", Tolerance_%=1%, Value2=0.1W, Value_Code=1k00, ValueDisplayed=1.00k
R18 R23: library part CMP-0022277-4, "RES, 2.49 k, 1%, 0.1 W, AEC-Q200 Grade 0, 0603", Manufacturer=Vishay-Dale, Power_W=100mW, Supplier Part Number 1=541-2.49KHCT-ND, TempCo="100 ppm/C", Tolerance_%=1%, Value2=0.1W, Value_Code=2k49, ValueDisplayed=2.49k
R19: library part CMP-0022628-4, "RES, 86.6 k, 1%, 0.1 W, AEC-Q200 Grade 0, 0603", Manufacturer=Vishay-Dale, Power_W=100mW, Supplier Part Number 1=541-86.6KHCT-ND, TempCo="100 ppm/C", Tolerance_%=1%, Value2=0.1W, Value_Code=86k6, ValueDisplayed=86.6k
R20 R21: library part CMP-0021998-4, "RES, 10.0 k, 1%, 0.1 W, AEC-Q200 Grade 0, 0603", Manufacturer=Vishay-Dale, Power_W=100mW, Supplier Part Number 1=541-10.0KHCT-ND, TempCo="100 ppm/C", Tolerance_%=1%, Value2=0.1W, Value_Code=10k0, ValueDisplayed=10.0k
R22: library part CMP-0021283-3, "RES, 49.9 k, 1%, 0.125 W, AEC-Q200 Grade 0, 0805", Manufacturer=Vishay-Dale, Power_W=125mW, Supplier Part Number 1=541-49.9KCCT-ND, TempCo="100 ppm/C", Tolerance_%=1%, Value2=0.125W, Value_Code=49k9, ValueDisplayed=49.9k
R24: library part CMP-0022410-4, "RES, 40.2 k, 1%, 0.1 W, AEC-Q200 Grade 0, 0603", Manufacturer=Vishay-Dale, Power_W=100mW, Supplier Part Number 1=541-40.2KHCT-ND, TempCo="100 ppm/C", Tolerance_%=1%, Value2=0.1W, Value_Code=40k2, ValueDisplayed=40.2k
R26: library part CMP-0022274-4, "RES, 2.32 k, 1%, 0.1 W, AEC-Q200 Grade 0, 0603", Manufacturer=Vishay-Dale, Power_W=100mW, Supplier Part Number 1=541-2.32KHCT-ND, TempCo="100 ppm/C", Tolerance_%=1%, Value2=0.1W, Value_Code=2k32, ValueDisplayed=2.32k
T1: library part CMP-0091023-1, "Flyback Transformer EFD25 12 Pins input:18-30Vin, output:56/1.25A, Aux:10.6V", Manufacturer=Coilcraft, Operating Temperature Range=to, Voltage_Isolation_Vrms=2500Vrms
U1: library part CMP-0085932-2, "2.2-MHz Wide Input Nonsynchronous Boost, Sepic, Flyback Controller, DSS0012B (WSON-12)", Alternate Manufacturer="Texas Instruments", Alternate PartNumber=LM51551DSST
U2: library part CMP-0006163-3, "Optocoupler, 3.75 kV, 80-160% CTR, SMT", Manufacturer=Vishay-Semiconductor, Supplier Part Number 1=VOS617A-7X001T-ND, Voltage_Isolation_Vrms=3.75kV
U3: library part CMP-0084729-1, "Programmable Shunt Regulator with Optimized Reference Current, DBZ0003A (SOT-23-3)", Alternate Manufacturer="Texas Instruments"

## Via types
v1: diameter 40, hole 18, Top Layer to Bottom Layer, 89 vias
v2: diameter 19.68, hole 7.87, Top Layer to Bottom Layer, 3 vias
